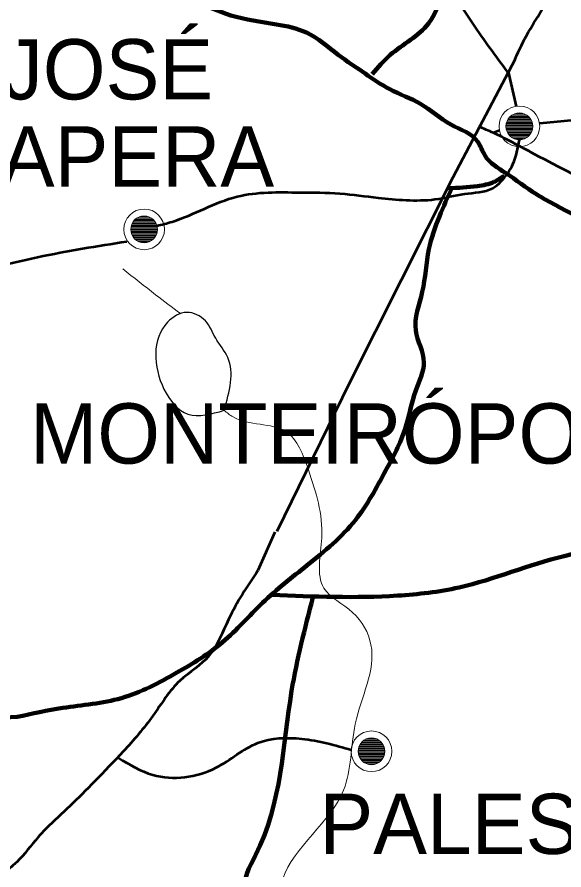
# Model space of a CAD drawing. Extents: x 512883 to 1063249, y 8784064 to 9081064.
# Drawn here: x 674490 to 688095, y 8927073 to 8948300 of the extents above; entities that cross this region are included whole.
import ezdxf

# ---------------------------------------------------------------- set-up
doc = ezdxf.new("R2010")
doc.units = 0
doc.header["$LTSCALE"] = 600
doc.linetypes.add('DOT_DASHED', pattern=[7.7, 5, -1.2, 0.3, -1.2])
for name, color, linetype, lineweight in [('10', 7, 'Continuous', 53), ('13', 7, 'Continuous', 90), ('20', 7, 'Continuous', 53), ('3', 7, 'Continuous', 25), ('4', 7, 'Continuous', 13), ('5', 7, 'Continuous', 13), ('60', 7, 'Continuous', 25)]:
    doc.layers.add(name, color=color, linetype=linetype, lineweight=lineweight)

msp = doc.modelspace()

# ---------------------------------------------------------------- linework, layer by layer
at = {"layer": '10'}
for p, q in [((686916.9, 8946073), (686716.2, 8946946.3)), ((686494.2, 8945478.8), (686344.1, 8945417.9)), ((680900.9, 8935478.2), (680484.1, 8934529.4))]:
    msp.add_line(p, q, dxfattribs=at)
msp.add_lwpolyline([(686879, 8947250.2), (685329.9, 8944307.9), (682756.7, 8939198.9), (680955.1, 8935497.3)], dxfattribs=at)
for points in [[(686879, 8947250.2), (687215.3, 8947932.8), (687572, 8948527.5), (687786, 8948956.6), (688076.4, 8949437.6)], [(661143.8, 8945556.2), (662407.6, 8946035.8), (663719.6, 8946067.1), (664857.5, 8945518.9), (666015.1, 8944949.5), (668384.9, 8943538.4), (670469.7, 8942009.1), (674994.8, 8942323.4), (677217.8, 8942716)], [(690354.9, 8942526.3), (689817.4, 8943269.9), (687295.1, 8944922.2), (686757.6, 8945211.3), (686340.8, 8945414.9), (685973.5, 8945577)], [(677966.5, 8943105.4), (678346.6, 8943206.6), (679964.3, 8943832.1), (681523.6, 8943935.6), (682522.3, 8943909.7), (683470.1, 8943801.1), (684168.2, 8943744.2), (684886.6, 8943764.9), (685625.5, 8943899.4), (686323.6, 8944044.2), (686695.5, 8944416.5), (686822.9, 8944638.8), (686986.1, 8945247.1)], [(680484.1, 8934529.4), (679750.3, 8933309.1), (679271.3, 8932409.3), (678542.7, 8931783.6), (677870.1, 8930909.7), (677131.2, 8930020.3), (676417.8, 8929275.7), (675796.2, 8928655.1), (675011.5, 8927884.7), (674481.5, 8927269.3), (674252.2, 8927072.8)]]:
    msp.add_spline(points, degree=3, dxfattribs=at)
at = {"layer": '13'}
for points in [[(687717.5, 8953534.4), (685899.8, 8950515.2), (685172.7, 8949145.3), (684725.3, 8948138.9), (683774.5, 8947356.2), (683327, 8946880.9)], [(697917.7, 8940030.2), (695483.7, 8940642.8), (693475.6, 8941153.4), (692502.1, 8941214.7), (691508.2, 8941480.2), (690352, 8942072.5), (689439.3, 8942726), (688425.1, 8943338.7), (687411, 8943890.1), (686640.2, 8944421.1), (686133.1, 8944850), (685950.6, 8945197.2), (685281.2, 8945626.1), (684530.7, 8946136.7), (683760, 8946504.3), (683151.5, 8946892.3), (682482.1, 8947362.1), (681691.1, 8947913.5), (680940.6, 8948117.7), (679804.7, 8948342.4), (678932.6, 8948669.2), (678381, 8948825.9)], [(674490.5, 8930880.6), (672043.1, 8930925.7), (668845.2, 8932294), (665328.7, 8934774.4), (663896.9, 8936642.6), (661883.5, 8938670.4), (659757.9, 8940179.9), (657908.6, 8942328.8), (656340.6, 8944429.5), (655853.4, 8945212.2), (655718.6, 8945507.2)], [(685224.7, 8944040.7), (685943.8, 8944092.2), (686354.8, 8944195), (686611.6, 8944349.2)], [(674490.5, 8930880.6), (675626.4, 8931105.2), (677086.8, 8931350.3), (678466, 8931983.4), (679601.9, 8932739.1), (680595.8, 8933719.4), (681711.4, 8934658.9), (682908.1, 8935782.1), (683658.6, 8937007.5), (684145.3, 8938049.1), (684409, 8939009), (684611.9, 8939703.4), (684409, 8940499.9), (684571.3, 8941459.8), (684733.6, 8942521.8), (684997.2, 8943338.7), (685312.5, 8944057.4)], [(680828.7, 8933919), (683954.5, 8933899.9), (685486.5, 8934104.2), (688100.7, 8934885), (691225.8, 8935479.3), (693370.2, 8936322.6), (696113.8, 8936977.5)], [(681850.5, 8933861.5), (681321, 8931529.8), (680425, 8927444), (680180.5, 8926536.1), (680282.8, 8926350.2), (680670.9, 8926329), (682182.8, 8925955.3), (684185.2, 8925312.7), (684696.1, 8925126.2), (684982.2, 8924919.4), (685125.4, 8924568.3), (686740.3, 8923038.6), (687253.7, 8921944)]]:
    msp.add_spline(points, degree=3, dxfattribs=at)
at = {"layer": '20'}
for points in [[(683363, 8951685.3), (684253.4, 8950848.9), (685091, 8949362.2), (685827.1, 8948131.8), (686690.1, 8946927.1)], [(687492.6, 8945658.8), (688879.6, 8945806.7), (690884.8, 8946191.2), (692737.8, 8946575.7), (694590.7, 8946729.4), (697823.6, 8947505.2)], [(677011.7, 8929863), (677867, 8929439.7), (679440.8, 8929619.1), (680481.5, 8930234.3), (681572.9, 8930336.8), (682804.7, 8930063.7)]]:
    msp.add_spline(points, degree=3, dxfattribs=at)
at = {"layer": '3', "lineweight": 13}
for points in [[(678553.7, 8940923.5), (677937.3, 8941388.8), (677120.1, 8942034.4)], [(679643.2, 8938512.8), (678742.1, 8938418.6), (678144.9, 8939041.5), (678233.9, 8940707), (678715.6, 8940949.3), (679174.8, 8940739.2), (679432.7, 8940304.7), (679730.3, 8939828.7), (679643.2, 8938512.8)], [(677984.7, 8918570.3), (678406.7, 8920626.1), (679076, 8922265.5), (680680.5, 8922887.9), (681054.8, 8925497.1), (681102.1, 8926854.5), (682615, 8929061.9), (682904, 8930705), (683294.9, 8932676.2), (682838.8, 8933483), (682121.5, 8934086.4), (682068.2, 8935341.9), (681737, 8937032.1), (681181.6, 8937983.8), (679862.5, 8938346.1), (679643.2, 8938512.8)]]:
    msp.add_spline(points, degree=3, dxfattribs=at)
at = {"layer": '3'}
msp.add_spline([(679643.2, 8938512.8), (678742.1, 8938418.6), (678144.9, 8939041.5), (678233.9, 8940707), (678715.6, 8940949.3), (679174.8, 8940739.2), (679432.7, 8940304.7), (679730.3, 8939828.7), (679643.2, 8938512.8)], degree=3, dxfattribs=at)
at = {"layer": '4', "linetype": 'DOT_DASHED', "lineweight": 25}
msp.add_spline([(649305.2, 8929224.6), (649906.8, 8931577.6), (650496.3, 8933626.8), (651745.4, 8937244.4), (650026.3, 8938890.1), (648813.5, 8940627.9), (648150.6, 8942602.8), (647468, 8944598.9), (647078.2, 8946150.5), (647172.8, 8947711.3), (647617.2, 8948659.4), (647803.9, 8950739.1), (648059.7, 8953213.2), (648283, 8955125.2), (648539.5, 8955786.1), (649780.9, 8959049.5), (650736.6, 8960318.9), (652033.8, 8961517.6), (652561.8, 8963526.7), (652858.7, 8964186.5), (654217.2, 8965425.5), (654887, 8966535), (655308.9, 8967379.5), (655992.8, 8969134.7), (656859.3, 8970010.3), (658218.7, 8971290.9), (659592.4, 8972300.3), (660729.1, 8973544.6), (661684.5, 8973876.1), (663627.8, 8975101.2), (664866.2, 8976384.7), (665579.7, 8976722), (666723.4, 8977361.8), (667655.3, 8978465), (668765, 8979397.3), (670276.7, 8980257.5), (670730.7, 8980726), (673194.5, 8982689), (673989.8, 8984003.9), (674145.8, 8985605), (673414.7, 8987227.2), (672983.2, 8988717.2), (672885.3, 8990699.4), (673627, 8992328.2), (674021.8, 8993777.8), (674826.7, 8995530.1), (675940.8, 8997587.7), (677572.3, 9000237.4), (677647.8, 9000923.4), (677610.1, 9001966.4), (678954.8, 9003497.5), (679698.8, 9005230.4), (681172.8, 9006216.6), (682944.3, 9006966.4), (683427.6, 9007851.1), (682741.8, 9009701.4), (681771.4, 9011454.3), (681734.9, 9013476.8), (681996.3, 9015283.8), (682991, 9016489.8)], degree=3, dxfattribs=at)
at = {"layer": '5'}
for p, q in [((686765.2, 8945828.9), (687206.8, 8945828.9)), ((686804.8, 8945858.9), (687167.2, 8945858.9)), ((686862.1, 8945888.9), (687109.9, 8945888.9)), ((686655.7, 8945618.9), (687316.3, 8945618.9)), ((686660.5, 8945648.9), (687311.5, 8945648.9)), ((686668.6, 8945678.9), (687303.4, 8945678.9)), ((686679.4, 8945708.9), (687292.6, 8945709.2)), ((686693.8, 8945738.9), (687278.5, 8945738.9)), ((686712.1, 8945768.9), (687260.2, 8945768.9)), ((686736.1, 8945798.9), (687236.5, 8945798.9)), ((686653.6, 8945588.9), (687318.4, 8945588.9)), ((686654.2, 8945558.9), (687318.1, 8945558.9)), ((686657.2, 8945528.9), (687314.8, 8945528.9)), ((686663.2, 8945498.9), (687308.8, 8945498.9)), ((686672.2, 8945468.9), (687299.8, 8945468.9)), ((686684.8, 8945438.9), (687287.5, 8945439.2)), ((686700.7, 8945408.9), (687271.3, 8945408.9)), ((686721.4, 8945378.9), (687250.9, 8945379.2)), ((686746.6, 8945348.7), (687225.7, 8945348.9)), ((686779.9, 8945318.9), (687192.1, 8945318.9)), ((686824.9, 8945288.9), (687147.1, 8945288.9)), ((686898.7, 8945258.9), (687073, 8945258.9)), ((677469.8, 8943294.1), (677832.2, 8943294.1)), ((677527.1, 8943324.1), (677774.9, 8943324.1)), ((677325.5, 8943084.1), (677976.5, 8943084.1)), ((677333.6, 8943114.1), (677968.4, 8943114.1)), ((677344.4, 8943144.1), (677957.6, 8943144.4)), ((677358.8, 8943174.1), (677943.5, 8943174.1)), ((677377.1, 8943204.1), (677925.2, 8943204.1)), ((677401.1, 8943234.1), (677901.5, 8943234.1)), ((677430.2, 8943264.1), (677871.8, 8943264.1)), ((677318.6, 8943024.1), (677983.4, 8943024.1)), ((677319.2, 8942994.1), (677983.1, 8942994.1)), ((677320.7, 8943054.1), (677981.3, 8943054.1)), ((677322.2, 8942964.1), (677979.8, 8942964.1)), ((677328.2, 8942934.1), (677973.8, 8942934.1)), ((677337.2, 8942904.1), (677964.8, 8942904.1)), ((677349.8, 8942874.1), (677952.5, 8942874.4)), ((677365.7, 8942844.1), (677936.3, 8942844.1)), ((677386.4, 8942814.1), (677915.9, 8942814.4)), ((677411.6, 8942783.8), (677890.7, 8942784.1)), ((677444.9, 8942754.1), (677857.1, 8942754.1)), ((677489.9, 8942724.1), (677812.1, 8942724.1)), ((677563.7, 8942694.1), (677738, 8942694.1)), ((683183.1, 8930334.5), (683430.9, 8930334.5)), ((682989.6, 8930124.5), (683624.4, 8930124.5)), ((683000.4, 8930154.5), (683613.6, 8930154.8)), ((683014.8, 8930184.5), (683599.5, 8930184.5)), ((683033.1, 8930214.5), (683581.2, 8930214.5)), ((683057.1, 8930244.5), (683557.5, 8930244.5)), ((683086.2, 8930274.5), (683527.8, 8930274.5)), ((683125.8, 8930304.5), (683488.2, 8930304.5)), ((682974.6, 8930034.5), (683639.4, 8930034.5)), ((682975.2, 8930004.5), (683639.1, 8930004.5)), ((682976.7, 8930064.5), (683637.3, 8930064.5)), ((682978.2, 8929974.5), (683635.8, 8929974.5)), ((682981.5, 8930094.5), (683632.5, 8930094.5)), ((682984.2, 8929944.5), (683629.8, 8929944.5)), ((682993.2, 8929914.5), (683620.8, 8929914.5)), ((683005.8, 8929884.5), (683608.5, 8929884.8)), ((683021.7, 8929854.5), (683592.3, 8929854.5)), ((683042.4, 8929824.5), (683571.9, 8929824.8)), ((683067.6, 8929794.2), (683546.7, 8929794.5)), ((683100.9, 8929764.5), (683513.1, 8929764.5)), ((683145.9, 8929734.5), (683468.1, 8929734.5)), ((683219.7, 8929704.5), (683394, 8929704.5))]:
    msp.add_line(p, q, dxfattribs=at)
for centre, radius in [((686986.1, 8945579.9), 506.1), ((686986.1, 8945579.9), 332.9), ((677651, 8943015.1), 506.1), ((677651, 8943015.1), 332.9), ((683307.1, 8930025.5), 506.1), ((683307.1, 8930025.5), 332.9)]:
    msp.add_circle(centre, radius, dxfattribs=at)
at = {"layer": '60', "lineweight": 13}
for points in [[(678553.7, 8940923.5), (677937.3, 8941388.8), (677120.1, 8942034.4)], [(679643.2, 8938512.8), (678742.1, 8938418.6), (678144.9, 8939041.5), (678233.9, 8940707), (678715.6, 8940949.3), (679174.8, 8940739.2), (679432.7, 8940304.7), (679730.3, 8939828.7), (679643.2, 8938512.8)], [(677984.7, 8918570.3), (678406.7, 8920626.1), (679076, 8922265.5), (680680.5, 8922887.9), (681054.8, 8925497.1), (681102.1, 8926854.5), (682615, 8929061.9), (682904, 8930705), (683294.9, 8932676.2), (682838.8, 8933483), (682121.5, 8934086.4), (682068.2, 8935341.9), (681737, 8937032.1), (681181.6, 8937983.8), (679862.5, 8938346.1), (679643.2, 8938512.8)]]:
    msp.add_spline(points, degree=3, dxfattribs=at)
at = {"layer": '60'}
msp.add_spline([(679643.2, 8938512.8), (678742.1, 8938418.6), (678144.9, 8939041.5), (678233.9, 8940707), (678715.6, 8940949.3), (679174.8, 8940739.2), (679432.7, 8940304.7), (679730.3, 8939828.7), (679643.2, 8938512.8)], degree=3, dxfattribs=at)

# ---------------------------------------------------------------- texts
at = {"layer": '5'}
for s, p in [('SÃO JOSÉ', (669335.4, 8946249.6)), ('DA TAPERA', (669516.3, 8944081.7)), ('MONTEIRÓPOLIS', (674815.8, 8937186.6)), ('PALESTINA', (682012.2, 8927470.7))]:
    msp.add_text(s, height=1500, dxfattribs=at).set_placement(p)

doc.saveas('drawing.dxf')
